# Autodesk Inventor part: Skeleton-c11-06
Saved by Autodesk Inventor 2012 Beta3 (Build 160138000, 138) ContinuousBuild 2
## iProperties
Created: 2011-01
Part Number: Skeleton-c11-06
Material: Default
Document SubType Name: Modeling
Designer: Beta-8540w
Density: 1 g/cm^3
_SkeletonDoc: Frame Skeleton File
_Version: 15.0.0
Author: Beta-8540w
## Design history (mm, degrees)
sketch "Reference Skeleton"
  geometry: L1 through (404.523, 1164.395) direction (1, 0); L2 through (325.691, 1070.446) direction (1, 0); 34 other entities
  constraints: 10 horizontal
